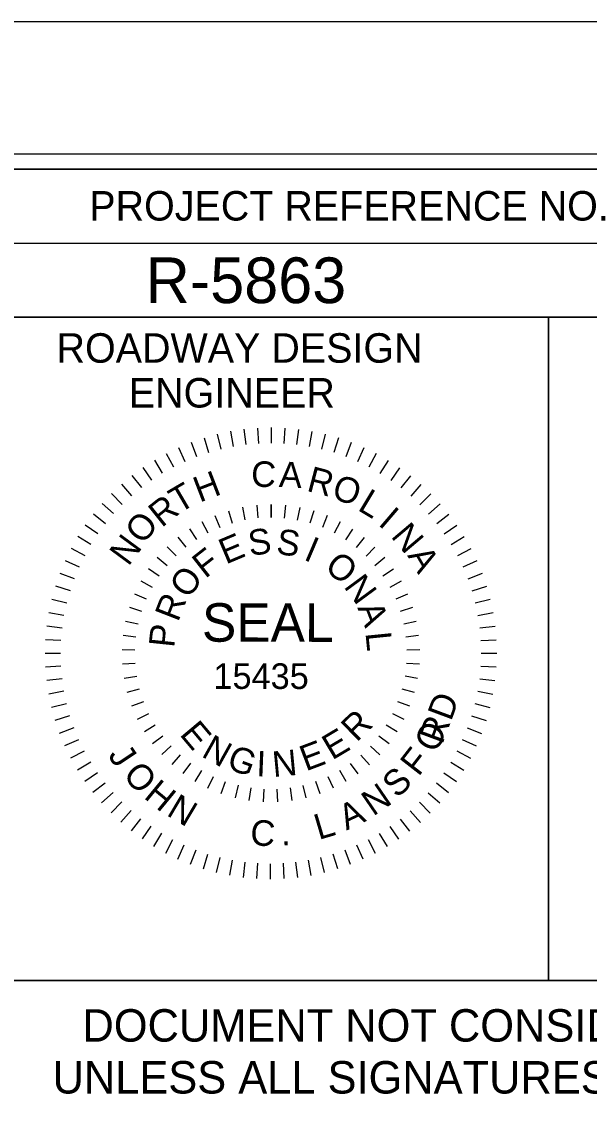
# Model space of a CAD drawing. Extents: x 557032 to 558840, y 515971 to 517218.
# Drawn here: x 558510.2 to 558606.3, y 517032.6 to 517218.2 of the extents above; entities that cross this region are included whole.
import ezdxf

# ---------------------------------------------------------------- set-up
doc = ezdxf.new("R2010")
doc.units = 0
for name, color, linetype in [('Old_Level_21', 7, 'Continuous'), ('Sheet Cutting Line CELL', 7, 'Continuous'), ('Sheet Data Field CELL', 7, 'Continuous'), ('Sheet Plot Border Inside CELL', 7, 'Continuous'), ('Sheet Plot Border Outside CELL', 7, 'Continuous'), ('Sheet Profile CELL', 7, 'Continuous'), ('Sheet Profile Grid Major CELL', 7, 'Continuous'), ('Sheet Sticker Exception Certification CELL', 7, 'Continuous')]:
    doc.layers.add(name, color=color, linetype=linetype)

msp = doc.modelspace()

# ---------------------------------------------------------------- linework, layer by layer
at = {"layer": 'Old_Level_21'}
for p, q in [((558547.84, 517149.1), (558548.15, 517146.51)), ((558550.14, 517149.3), (558550.3, 517146.7)), ((558552.46, 517149.37), (558552.45, 517146.76)), ((558554.77, 517149.3), (558554.61, 517146.69)), ((558557.07, 517149.08), (558556.75, 517146.5)), ((558541.07, 517147.66), (558541.84, 517145.16)), ((558543.3, 517148.27), (558543.91, 517145.74)), ((558545.56, 517148.75), (558546.02, 517146.19)), ((558559.35, 517148.74), (558558.88, 517146.17)), ((558561.61, 517148.25), (558560.99, 517145.72)), ((558563.84, 517147.62), (558563.06, 517145.13)), ((558536.75, 517146.02), (558537.81, 517143.64)), ((558538.88, 517146.9), (558539.81, 517144.46)), ((558566.02, 517146.87), (558565.09, 517144.43)), ((558568.15, 517145.97), (558567.08, 517143.6)), ((558532.65, 517143.88), (558534, 517141.65)), ((558534.67, 517145.01), (558535.87, 517142.7)), ((558570.23, 517144.96), (558569.02, 517142.65)), ((558572.25, 517143.82), (558570.89, 517141.59)), ((558530.71, 517142.63), (558532.19, 517140.48)), ((558574.18, 517142.57), (558572.7, 517140.42)), ((558528.85, 517141.26), (558530.45, 517139.2)), ((558576.04, 517141.19), (558574.43, 517139.14)), ((558525.38, 517138.2), (558527.22, 517136.35)), ((558527.06, 517139.78), (558528.79, 517137.83)), ((558577.82, 517139.71), (558576.09, 517137.76)), ((558579.5, 517138.12), (558577.65, 517136.28)), ((558523.79, 517136.52), (558525.74, 517134.79)), ((558550, 517136.21), (558550.21, 517134.05)), ((558552.44, 517136.32), (558552.43, 517134.15)), ((558552.43, 517134.15), (558552.44, 517136.32)), ((558554.87, 517136.2), (558554.66, 517134.04)), ((558581.08, 517136.44), (558579.13, 517134.71)), ((558522.31, 517134.74), (558524.36, 517133.13)), ((558542.92, 517134.48), (558543.74, 517132.46)), ((558545.22, 517135.28), (558545.84, 517133.2)), ((558547.59, 517135.86), (558548, 517133.73)), ((558557.28, 517135.85), (558556.86, 517133.71)), ((558559.65, 517135.26), (558559.02, 517133.18)), ((558561.95, 517134.45), (558561.12, 517132.44)), ((558582.56, 517134.66), (558580.5, 517133.06)), ((558520.94, 517132.89), (558523.08, 517131.4)), ((558540.71, 517133.45), (558541.72, 517131.53)), ((558564.15, 517133.42), (558563.14, 517131.5)), ((558583.93, 517132.8), (558581.78, 517131.32)), ((558519.68, 517130.95), (558521.91, 517129.59)), ((558536.63, 517130.79), (558537.99, 517129.09)), ((558538.61, 517132.22), (558539.8, 517130.4)), ((558566.25, 517132.18), (558565.06, 517130.36)), ((558568.22, 517130.75), (558566.86, 517129.05)), ((558585.18, 517130.86), (558582.95, 517129.51)), ((558518.54, 517128.93), (558520.85, 517127.72)), ((558534.81, 517129.17), (558536.33, 517127.62)), ((558570.04, 517129.13), (558568.52, 517127.57)), ((558586.31, 517128.84), (558584, 517127.63)), ((558517.53, 517126.85), (558519.9, 517125.78)), ((558533.15, 517127.39), (558534.81, 517125.99)), ((558571.7, 517127.34), (558570.04, 517125.94)), ((558531.66, 517125.46), (558533.45, 517124.22)), ((558573.18, 517125.4), (558571.39, 517124.17)), ((558587.32, 517126.76), (558584.94, 517125.69)), ((558516.64, 517124.72), (558519.08, 517123.79)), ((558530.38, 517123.39), (558532.27, 517122.33)), ((558574.46, 517123.33), (558572.56, 517122.27)), ((558588.2, 517124.62), (558585.76, 517123.7)), ((558515.88, 517122.54), (558518.37, 517121.76)), ((558588.96, 517122.44), (558586.46, 517121.67)), ((558515.26, 517120.31), (558517.79, 517119.69)), ((558529.29, 517121.21), (558531.28, 517120.34)), ((558575.54, 517121.14), (558573.55, 517120.28)), ((558589.57, 517120.21), (558587.04, 517119.59)), ((558514.77, 517118.05), (558517.33, 517117.58)), ((558528.43, 517118.93), (558530.49, 517118.26)), ((558576.4, 517118.86), (558574.33, 517118.2)), ((558590.05, 517117.95), (558587.49, 517117.48)), ((558514.42, 517115.77), (558517.01, 517115.45)), ((558527.78, 517116.58), (558529.9, 517116.11)), ((558577.04, 517116.51), (558574.91, 517116.05)), ((558527.37, 517114.18), (558529.52, 517113.92)), ((558577.44, 517114.11), (558575.29, 517113.85)), ((558590.4, 517115.66), (558587.81, 517115.35)), ((558514.21, 517113.47), (558516.81, 517113.31)), ((558590.6, 517113.36), (558588, 517113.21)), ((558514.13, 517111.16), (558516.74, 517111.15)), ((558527.19, 517111.75), (558529.36, 517111.69)), ((558577.62, 517111.68), (558575.45, 517111.63)), ((558590.67, 517111.05), (558588.06, 517111.05)), ((558514.2, 517108.84), (558516.8, 517109)), ((558527.24, 517109.31), (558529.41, 517109.46)), ((558577.56, 517109.24), (558575.39, 517109.4)), ((558590.6, 517108.74), (558587.99, 517108.9)), ((558514.41, 517106.54), (558517, 517106.85)), ((558527.54, 517106.89), (558529.68, 517107.25)), ((558575.13, 517107.27), (558577.27, 517106.9)), ((558590.38, 517106.44), (558587.8, 517106.75)), ((558514.75, 517104.26), (558517.32, 517104.72)), ((558528.06, 517104.51), (558530.15, 517105.08)), ((558576.73, 517104.44), (558574.63, 517105.01)), ((558590.03, 517104.15), (558587.47, 517104.62)), ((558528.81, 517102.19), (558530.84, 517102.96)), ((558575.97, 517102.12), (558573.94, 517102.9)), ((558515.23, 517102), (558517.77, 517102.61)), ((558529.78, 517099.96), (558531.73, 517100.92)), ((558574.99, 517099.89), (558573.05, 517100.86)), ((558589.55, 517101.89), (558587.01, 517102.52)), ((558515.85, 517099.77), (558518.34, 517100.54)), ((558588.92, 517099.66), (558586.43, 517100.44)), ((558516.6, 517097.58), (558519.04, 517098.51)), ((558530.96, 517097.83), (558532.81, 517098.97)), ((558573.81, 517097.77), (558571.96, 517098.91)), ((558588.17, 517097.48), (558585.73, 517098.41)), ((558517.49, 517095.45), (558519.86, 517096.51)), ((558532.34, 517095.81), (558534.07, 517097.13)), ((558533.91, 517093.95), (558535.5, 517095.43)), ((558570.85, 517093.9), (558569.26, 517095.38)), ((558572.42, 517095.76), (558570.69, 517097.08)), ((558587.27, 517095.35), (558584.9, 517096.42)), ((558518.49, 517093.37), (558520.8, 517094.57)), ((558535.65, 517092.25), (558537.09, 517093.87)), ((558569.1, 517092.2), (558567.66, 517093.83)), ((558586.26, 517093.27), (558583.95, 517094.49)), ((558519.62, 517091.35), (558521.86, 517092.7)), ((558537.55, 517090.72), (558538.83, 517092.48)), ((558567.2, 517090.68), (558565.92, 517092.44)), ((558585.12, 517091.26), (558582.89, 517092.61)), ((558520.88, 517089.41), (558523.02, 517090.89)), ((558539.58, 517089.38), (558540.69, 517091.25)), ((558541.74, 517088.25), (558542.66, 517090.22)), ((558563, 517088.22), (558562.08, 517090.19)), ((558565.16, 517089.35), (558564.06, 517091.22)), ((558583.87, 517089.32), (558581.72, 517090.8)), ((558522.24, 517087.55), (558524.3, 517089.15)), ((558544, 517087.32), (558544.72, 517089.37)), ((558546.84, 517088.73), (558546.32, 517086.62)), ((558548.72, 517086.15), (558549.04, 517088.3)), ((558551.15, 517085.91), (558551.25, 517088.08)), ((558553.58, 517085.91), (558553.49, 517088.08)), ((558556.01, 517086.14), (558555.7, 517088.29)), ((558558.4, 517086.61), (558557.88, 517088.72)), ((558560.74, 517087.3), (558560.02, 517089.35)), ((558582.49, 517087.46), (558580.44, 517089.07)), ((558523.72, 517085.77), (558525.68, 517087.49)), ((558581.01, 517085.69), (558579.06, 517087.42)), ((558525.31, 517084.08), (558527.15, 517085.92)), ((558526.98, 517082.49), (558528.72, 517084.44)), ((558577.74, 517082.42), (558576.01, 517084.38)), ((558579.42, 517084.01), (558577.58, 517085.85)), ((558528.76, 517081.01), (558530.37, 517083.06)), ((558575.96, 517080.94), (558574.36, 517083)), ((558530.62, 517079.64), (558532.1, 517081.78)), ((558532.56, 517078.38), (558533.91, 517080.61)), ((558572.16, 517078.33), (558570.81, 517080.56)), ((558574.1, 517079.58), (558572.62, 517081.73)), ((558534.57, 517077.24), (558535.79, 517079.55)), ((558536.65, 517076.23), (558537.72, 517078.61)), ((558570.14, 517077.19), (558568.93, 517079.5)), ((558538.78, 517075.34), (558539.71, 517077.78)), ((558540.96, 517074.58), (558541.74, 517077.07)), ((558563.74, 517074.55), (558562.97, 517077.04)), ((558565.92, 517075.3), (558565, 517077.74)), ((558568.06, 517076.19), (558566.99, 517078.56)), ((558543.19, 517073.96), (558543.82, 517076.49)), ((558545.45, 517073.47), (558545.92, 517076.03)), ((558547.74, 517073.12), (558548.05, 517075.71)), ((558550.04, 517072.91), (558550.2, 517075.51)), ((558552.35, 517072.83), (558552.35, 517075.44)), ((558554.66, 517072.9), (558554.51, 517075.5)), ((558556.96, 517073.11), (558556.65, 517075.7)), ((558559.25, 517073.45), (558558.78, 517076.02)), ((558561.51, 517073.93), (558560.89, 517076.47))]:
    msp.add_line(p, q, dxfattribs=at)
at = {"layer": 'Sheet Cutting Line CELL'}
msp.add_line((558716.45, 517218.17), (557032.45, 517218.17), dxfattribs=at)
at = {"layer": 'Sheet Plot Border Inside CELL'}
msp.add_lwpolyline([(557045.45, 516140.62), (558711.95, 516140.62), (558711.95, 517195.72), (557045.45, 517195.72)], close=True, dxfattribs=at)
at = {"layer": 'Sheet Plot Border Outside CELL'}
msp.add_lwpolyline([(557032.45, 516118.17), (558716.45, 516118.17), (558716.45, 517218.17), (557032.45, 517218.17)], close=True, dxfattribs=at)
at = {"layer": 'Sheet Profile CELL'}
for p, q in [((558499.4, 517180.62), (558699.45, 517180.62)), ((558599.45, 517168.12), (558599.45, 517055.67))]:
    msp.add_line(p, q, dxfattribs=at)
for points in [[(558699.45, 517193.17), (557199.45, 517193.17), (557199.45, 516143.17), (558699.45, 516143.17)], [(558499.4, 517193.17), (558699.45, 517193.17), (558699.45, 517168.12), (558499.4, 517168.12)], [(558499.4, 517168.12), (558599.45, 517168.12), (558599.45, 517055.62), (558499.4, 517055.62)], [(558599.45, 517168.12), (558699.45, 517168.12), (558699.45, 517055.62), (558599.45, 517055.62)]]:
    msp.add_lwpolyline(points, close=True, dxfattribs=at)
at = {"layer": 'Sheet Profile Grid Major CELL'}
msp.add_lwpolyline([(557999.45, 517193.17), (558049.45, 517193.17), (558049.45, 516842.99), (558099.45, 516842.99), (558099.45, 517193.17), (558149.45, 517193.17), (558149.45, 516693.17), (558199.45, 516693.17), (558199.45, 517193.17), (558249.45, 517193.17), (558249.45, 516693.17), (558299.45, 516693.17), (558299.45, 517193.17), (558349.45, 517193.17), (558349.45, 516693.17), (558399.45, 516693.17), (558399.45, 517193.17), (558449.45, 517193.17), (558449.45, 516693.17), (558499.45, 516693.17), (558499.45, 517193.17), (558525.75, 517193.17)], dxfattribs=at)
at = {"layer": 'Sheet Sticker Exception Certification CELL'}
msp.add_line((558499.4, 517055.62), (558699.44, 517055.62), dxfattribs=at)
msp.add_line((558499.4, 517055.62), (558699.44, 517055.62), dxfattribs=at)

# ---------------------------------------------------------------- texts
at = {"layer": 'Old_Level_21'}
for s, height, rotation, p in [('C', 4.34, 357.2771, (558548.97, 517139.42)), ('A', 4.34, 357.2771, (558553.71, 517139.32)), ('H', 4.34, 20.9878, (558540.32, 517136.64)), ('R', 4.34, 345.2678, (558558.31, 517138.68)), ('T', 4.34, 30.4198, (558536.82, 517134.75)), ('O', 4.34, 342.211, (558562.52, 517137.42)), ('L', 4.34, 329.0747, (558566.94, 517135.48)), ('R', 4.34, 38.5807, (558533.89, 517132.32)), ('O', 4.34, 51.6375, (558530.74, 517129.4)), ('I', 4.34, 319.4993, (558570.44, 517132.95)), ('N', 4.34, 310.2048, (558572.61, 517130.9)), ('N', 4.34, 53.5969, (558528.24, 517125.74)), ('E', 4.34, 22.8645, (558544.76, 517126.14)), ('S', 4.34, 7.5683, (558548.84, 517127.62)), ('S', 4.34, 352.272, (558553.18, 517127.98)), ('I', 4.34, 336.9758, (558557.8, 517127.04)), ('F', 4.34, 38.1608, (558541.28, 517123.69)), ('O', 4.34, 321.6795, (558561.3, 517125.34)), ('A', 4.34, 300.4373, (558575.47, 517127.69)), ('O', 4.34, 53.457, (558538.39, 517120.19)), ('N', 4.34, 306.3833, (558564.64, 517122.42)), ('R', 4.34, 68.7533, (558536.66, 517116.29)), ('SEAL', 6.521, 359.9202, (558540.72, 517113.08)), ('A', 4.34, 291.0871, (558567.02, 517118.86)), ('P', 4.34, 84.0495, (558536, 517111.98)), ('L', 4.34, 275.7908, (558568.42, 517114.56)), ('15435', 4.344, 359.9202, (558542.66, 517105.08)), (' RD', 4.344, 69.5926, (558580.89, 517094.03)), ('R', 4.34, 44.4851, (558566.93, 517095.94)), ('E', 4.34, 309.9903, (558536.81, 517097.33)), ('O ', 4.344, 60.9198, (558580.25, 517094.01)), ('N', 4.34, 330.8453, (558540.46, 517093.7)), ('E', 4.34, 30.714, (558562.79, 517092.92)), ('G', 4.34, 339.6116, (558544.71, 517091.66)), ('E', 4.34, 20.7281, (558558.33, 517091.07)), ('F', 4.34, 52.1272, (558577.42, 517090.09)), ('J', 4.34, 303.8552, (558524.69, 517093.8)), ('I', 4.34, 357.7064, (558549.88, 517090.26)), ('N', 4.34, 5.336, (558552.83, 517090.11)), ('O', 4.34, 311.927, (558527.17, 517090.33)), ('S', 4.34, 43.2446, (558573.8, 517086.41)), ('H', 4.34, 320.5697, (558530.71, 517086.67)), ('N', 4.34, 34.362, (558569.73, 517083.4)), ('N', 4.34, 329.2423, (558534.55, 517083.73)), ('A', 4.34, 25.5393, (558565.21, 517081.04)), ('C', 4.34, 356.0101, (558548.8, 517078.62)), ('L', 4.34, 16.5368, (558560.51, 517079.45)), ('.', 4.34, 3.7525, (558554.19, 517078.5))]:
    msp.add_text(s, height=height, rotation=rotation, dxfattribs=at).set_placement(p)
at = {"layer": 'Sheet Data Field CELL'}
msp.add_text('R-5863   ', height=7.75, dxfattribs=at).set_placement((558531.18, 517170.48))
at = {"layer": 'Sheet Profile CELL'}
for s, height, p in [('PROJECT REFERENCE NO.', 5.0001, (558521.62, 517184.48)), ('ROADWAY DESIGN', 5.0001, (558516.07, 517160.38)), ('ENGINEER', 5, (558528.32, 517152.78))]:
    msp.add_text(s, height=height, dxfattribs=at).set_placement(p)
at = {"layer": 'Sheet Sticker Exception Certification CELL'}
for s, p in [('DOCUMENT NOT CONSIDERED FINAL', (558520.47, 517045.27)), ('DOCUMENT NOT CONSIDERED FINAL', (558520.47, 517045.27)), ('UNLESS ALL SIGNATURES COMPLETED', (558515.4, 517036.47)), ('UNLESS ALL SIGNATURES COMPLETED', (558515.4, 517036.47))]:
    msp.add_text(s, height=5.5, dxfattribs=at).set_placement(p)

doc.saveas('drawing.dxf')
